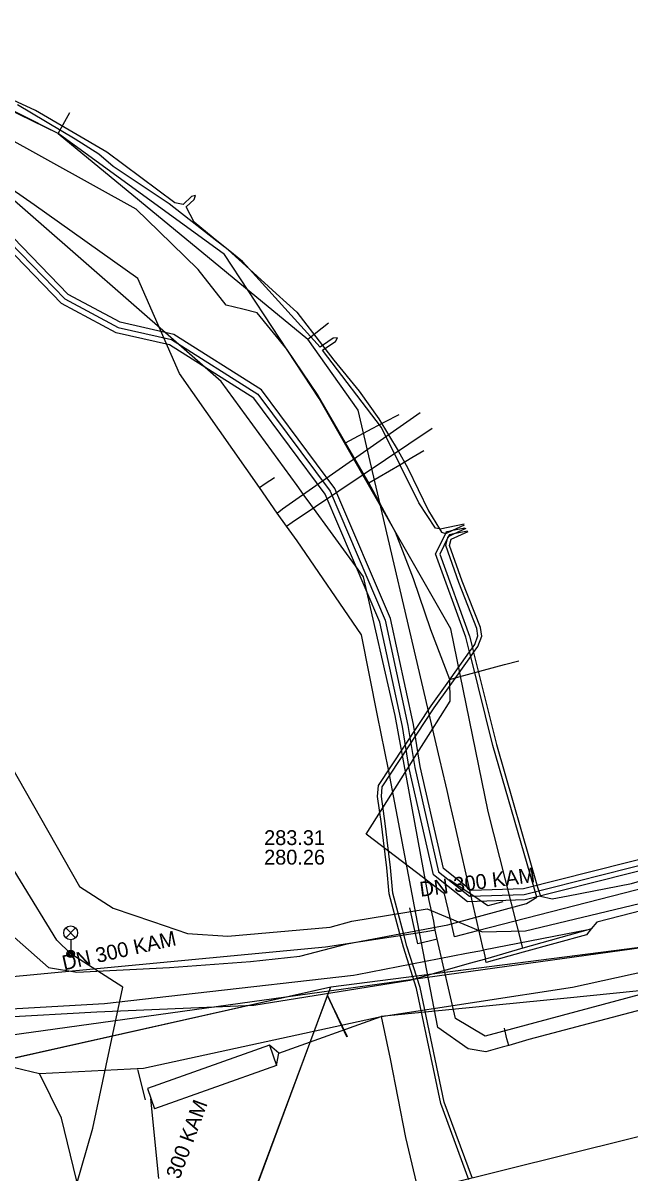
# Model space of a CAD drawing. Extents: x -599854 to -599675, y -1160809 to -1160543.
# Drawn here: x -599745.4 to -599712.8, y -1160609.7 to -1160547.9 of the extents above; entities that cross this region are included whole.
import ezdxf

# ---------------------------------------------------------------- set-up
doc = ezdxf.new("R2010")
doc.units = 0
for name, color, linetype in [('BKOM-ODVODNENI_trasa sítě', 7, 'Continuous'), ('BVK-KANALIZACE_ vyřazená trasa sítě', 7, 'Continuous'), ('BVK-VODOVOD_trasa sítě', 7, 'Continuous'), ('BVK-VODOVOD_trasa zrušené sítě', 7, 'Continuous'), ('CETIN_kabel podzemní', 7, 'Continuous'), ('CETIN_kabel podzemní neprovozovaný', 7, 'Continuous'), ('DESTOVA-NEPROVOZOVANA_popisy', 7, 'Continuous'), ('DESTOVA_trasa neprovozované sítě', 7, 'Continuous'), ('DPMB_kabel', 7, 'Continuous'), ('DPMB_kyneta', 7, 'Continuous'), ('DPMB_trolejové vedení-nosné lano', 7, 'Continuous'), ('DSP-JEDNOTNA-BVK_trasa sítě', 7, 'Continuous'), ('DSP-SDEL-MU_kabel', 7, 'Continuous'), ('EON-NN_kabel', 7, 'Continuous'), ('EON-NN_kabel zrušené sítě', 7, 'Continuous'), ('INNOGY-STL_trasa sítě', 7, 'Continuous'), ('TSB_kabel VO', 7, 'Continuous'), ('TSB_lampy VO', 7, 'Continuous')]:
    doc.layers.add(name, color=color, linetype=linetype)

msp = doc.modelspace()

# ---------------------------------------------------------------- linework, layer by layer
at = {"layer": 'BKOM-ODVODNENI_trasa sítě'}
for points in [[(-599728.85, -1160599.72), (-599710.68, -1160597.38)], [(-599747.14, -1160603.82), (-599728.85, -1160599.72)], [(-599734.15, -1160614), (-599732.8, -1160610.35), (-599728.85, -1160599.72)], [(-599727.954, -1160602.402), (-599729.02, -1160600.18)]]:
    msp.add_lwpolyline(points, dxfattribs=at)
at = {"layer": 'BVK-KANALIZACE_ vyřazená trasa sítě'}
msp.add_line((-599747.65, -1160602.53), (-599706.89, -1160596.87), dxfattribs=at)
at = {"layer": 'BVK-VODOVOD_trasa sítě'}
for points in [[(-599719.633, -1160602.967), (-599720.5, -1160603.21), (-599721.46, -1160603.05), (-599723.09, -1160601.91), (-599724.27, -1160595.77), (-599725.34, -1160590.19), (-599725.75, -1160588.02), (-599726.33, -1160585.11), (-599727.19, -1160580.77), (-599730.66, -1160575.71), (-599731.23, -1160574.92), (-599731.73, -1160574.22), (-599732.69, -1160572.85), (-599736.99, -1160566.71), (-599739.23, -1160561.6), (-599744.81, -1160557.63), (-599749.37, -1160554.46), (-599750.43, -1160553.69), (-599750.93, -1160553.31), (-599752.19, -1160552.51), (-599757.77, -1160552.65), (-599772.65, -1160553.34)], [(-599731.73, -1160574.22), (-599731.44, -1160574), (-599724.05, -1160568.815)], [(-599731.23, -1160574.92), (-599730.92, -1160574.72), (-599723.391, -1160569.647)], [(-599732.69, -1160572.85), (-599732.37, -1160572.63), (-599731.874, -1160572.301)], [(-599684.94, -1160592.81), (-599686.46, -1160593.25), (-599687.27, -1160594.52), (-599690.45, -1160595.29), (-599704.19, -1160598.9), (-599709.92, -1160600.36), (-599718.2, -1160602.56), (-599719.28, -1160602.87), (-599719.633, -1160602.967)], [(-599719.28, -1160602.87), (-599719.373, -1160602.508), (-599719.5, -1160601.95)]]:
    msp.add_lwpolyline(points, dxfattribs=at)
at = {"layer": 'BVK-VODOVOD_trasa zrušené sítě'}
for q in [(-599723.312, -1160596.189), (-599723.722, -1160596.755)]:
    msp.add_line((-599723.241, -1160596.669), q, dxfattribs=at)
for points in [[(-599723.312, -1160596.189), (-599723.552, -1160595.075), (-599725.385, -1160585.124), (-599727.088, -1160577.648), (-599730.061, -1160573.561), (-599730.185, -1160573.396), (-599730.663, -1160572.731), (-599734.747, -1160567.144), (-599747.147, -1160556.314), (-599750.794, -1160554.698), (-599754.863, -1160552.892), (-599773.118, -1160554.584), (-599787.156, -1160555.886), (-599789.075, -1160557.142), (-599798.149, -1160563.04), (-599806.144, -1160568.237), (-599808.168, -1160571.846), (-599815.66, -1160586.425), (-599816.228, -1160587.481)], [(-599684.94, -1160592.81), (-599720.55, -1160602.37), (-599722.14, -1160601.43), (-599723.128, -1160597.158), (-599723.241, -1160596.669)], [(-599723.128, -1160597.158), (-599723.488, -1160597.241), (-599724.166, -1160597.396), (-599724.288, -1160596.841), (-599724.591, -1160595.462)], [(-599723.722, -1160596.755), (-599729.139, -1160597.579), (-599769.626, -1160601.428)], [(-599679.2237, -1160599.5579), (-599732.933, -1160612.912), (-599785.657, -1160621.012)]]:
    msp.add_lwpolyline(points, dxfattribs=at)
at = {"layer": 'CETIN_kabel podzemní'}
for points in [[(-599743.51, -1160553.8), (-599747.69, -1160551.77), (-599759.07, -1160547.85)], [(-599743.51, -1160553.8), (-599742.89, -1160552.67)], [(-599743.51, -1160553.8), (-599730.08, -1160564.86)], [(-599730.08, -1160564.86), (-599728.98, -1160563.98)], [(-599722.66, -1160588.85), (-599722.98, -1160587.49), (-599727.38, -1160568.68), (-599730.08, -1160564.86)], [(-599747.4, -1160585.47), (-599742.37, -1160594.32), (-599740.56, -1160595.49), (-599738.44, -1160596.21), (-599736.55, -1160596.84), (-599734.39, -1160596.99), (-599728.89, -1160596.5), (-599727.72, -1160596.19), (-599723.67, -1160595.52), (-599720.71, -1160596.76), (-599718.38, -1160596.71), (-599712.25, -1160595.23), (-599710.48, -1160595.36)], [(-599722.18, -1160590.96), (-599722.42, -1160589.89), (-599722.59, -1160589.16), (-599722.66, -1160588.85)], [(-599720.64, -1160597.74), (-599721.23, -1160595.16), (-599722.18, -1160590.96)], [(-599710.85, -1160595.28), (-599714.54, -1160596.23), (-599714.84, -1160596.6)], [(-599714.84, -1160596.6), (-599715.1, -1160596.91), (-599718.5, -1160597.86), (-599720.49, -1160598.41), (-599720.53, -1160598.22)], [(-599720.64, -1160597.74), (-599720.53, -1160598.22)]]:
    msp.add_lwpolyline(points, dxfattribs=at)
at = {"layer": 'CETIN_kabel podzemní neprovozovaný'}
for points in [[(-599720.38, -1160590.29), (-599722.4, -1160580.45), (-599729.47, -1160568.06), (-599734.57, -1160560.31), (-599743.51, -1160553.8), (-599747.69, -1160551.7), (-599754.14, -1160548.99)], [(-599718.51, -1160597.64), (-599720.38, -1160590.29)], [(-599715.01, -1160596.65), (-599720.64, -1160597.74)], [(-599715.01, -1160596.65), (-599718.51, -1160597.64)], [(-599714.84, -1160596.6), (-599715.01, -1160596.65)], [(-599736.15, -1160600.06), (-599727.62, -1160599.09), (-599727.43, -1160599.05), (-599721.54, -1160597.91), (-599720.64, -1160597.74)], [(-599718.51, -1160597.64), (-599720.53, -1160598.22)], [(-599720.53, -1160598.22), (-599721.4, -1160598.46), (-599724.59, -1160599.37), (-599732.98, -1160600.73), (-599735.95, -1160600.85), (-599741.43, -1160601.08), (-599746.54, -1160601.36), (-599746.99, -1160601.21), (-599747.63, -1160600.99)], [(-599747.63, -1160600.99), (-599741.02, -1160600.62), (-599736.15, -1160600.06)]]:
    msp.add_lwpolyline(points, dxfattribs=at)
at = {"layer": 'DESTOVA-NEPROVOZOVANA_popisy'}
msp.add_line((-599732.433, -1160593.139), (-599732.433, -1160593.139), dxfattribs=at)
at = {"layer": 'DESTOVA_trasa neprovozované sítě'}
for p, q in [((-599747.14, -1160603.82), (-599728.85, -1160599.72)), ((-599727.98, -1160602.4), (-599729.021, -1160600.181))]:
    msp.add_line(p, q, dxfattribs=at)
for points in [[(-599728.85, -1160599.72), (-599711.672, -1160597.508), (-599710.68, -1160597.38)], [(-599734.15, -1160614), (-599732.963, -1160610.803), (-599732.796, -1160610.353), (-599729.021, -1160600.181), (-599728.85, -1160599.72)]]:
    msp.add_lwpolyline(points, dxfattribs=at)
at = {"layer": 'DPMB_kabel'}
for points in [[(-599746.11, -1160559.64), (-599743.15, -1160562.7), (-599740.29, -1160564.24), (-599737.41, -1160564.89), (-599732.78, -1160567.82), (-599728.89, -1160573.05), (-599725.931, -1160579.993), (-599724.7, -1160585.65), (-599724.33, -1160587.91), (-599723.05, -1160593.52), (-599721.395, -1160594.843), (-599718.44, -1160594.74), (-599712.79, -1160593.31), (-599697.24, -1160589.45), (-599689.48, -1160587.43), (-599686.51, -1160586.61), (-599685.46, -1160586.78), (-599682.03, -1160589.19), (-599679.2237, -1160588.477)], [(-599746.11, -1160559.64), (-599743.15, -1160562.7), (-599740.29, -1160564.24), (-599737.41, -1160564.89), (-599732.78, -1160567.82), (-599728.89, -1160573.05), (-599725.931, -1160579.993), (-599724.7, -1160585.65), (-599724.33, -1160587.91), (-599723.05, -1160593.52), (-599721.395, -1160594.843), (-599718.44, -1160594.74), (-599712.79, -1160593.31), (-599697.24, -1160589.45), (-599689.48, -1160587.43), (-599686.51, -1160586.61), (-599685.46, -1160586.78), (-599682.03, -1160589.19), (-599679.2237, -1160588.477)], [(-599679.2237, -1160588.1676), (-599681.97, -1160588.865), (-599685.344, -1160586.495), (-599686.527, -1160586.303), (-599689.558, -1160587.14), (-599697.314, -1160589.159), (-599712.863, -1160593.019), (-599718.483, -1160594.441), (-599721.294, -1160594.539), (-599722.781, -1160593.351), (-599724.035, -1160587.852), (-599724.405, -1160585.594), (-599725.644, -1160579.901), (-599728.628, -1160572.9), (-599732.573, -1160567.596), (-599737.293, -1160564.609), (-599740.184, -1160563.956), (-599742.967, -1160562.458), (-599745.93, -1160559.394)], [(-599679.2237, -1160588.1676), (-599681.97, -1160588.865), (-599685.344, -1160586.495), (-599686.527, -1160586.303), (-599689.558, -1160587.14), (-599697.314, -1160589.159), (-599712.863, -1160593.019), (-599718.483, -1160594.441), (-599721.294, -1160594.539), (-599722.781, -1160593.351), (-599724.035, -1160587.852), (-599724.405, -1160585.594), (-599725.644, -1160579.901), (-599728.628, -1160572.9), (-599732.573, -1160567.596), (-599737.293, -1160564.609), (-599740.184, -1160563.956), (-599742.967, -1160562.458), (-599745.93, -1160559.394)]]:
    msp.add_lwpolyline(points, dxfattribs=at)
at = {"layer": 'DPMB_kyneta'}
msp.add_lwpolyline([(-599679.2237, -1160588.7865), (-599682.09, -1160589.515), (-599685.576, -1160587.065), (-599686.493, -1160586.917), (-599689.402, -1160587.72), (-599697.166, -1160589.741), (-599712.717, -1160593.601), (-599718.397, -1160595.039), (-599721.496, -1160595.147), (-599723.319, -1160593.689), (-599724.625, -1160587.968), (-599724.995, -1160585.706), (-599726.218, -1160580.085), (-599729.152, -1160573.2), (-599732.987, -1160568.044), (-599737.527, -1160565.171), (-599740.396, -1160564.524), (-599743.333, -1160562.942), (-599746.29, -1160559.886), (-599753.886, -1160556.123), (-599765.587, -1160554.421), (-599775.611, -1160554.72)], dxfattribs=at)
at = {"layer": 'DPMB_trolejové vedení-nosné lano'}
for points in [[(-599715.84, -1160599.73), (-599702.95, -1160596.9)], [(-599702.52, -1160598.95), (-599716.14, -1160600.32)], [(-599726.14, -1160601.32), (-599715.84, -1160599.73)], [(-599716.14, -1160600.32), (-599726.14, -1160601.32)], [(-599738.93, -1160604.09), (-599726.14, -1160601.32)], [(-599731.645, -1160603.286), (-599726.14, -1160601.32)], [(-599726.14, -1160601.32), (-599725.66, -1160603.6)], [(-599751.26, -1160602.76), (-599744.51, -1160604.39)], [(-599732.152, -1160602.853), (-599738.714, -1160605.195)], [(-599732.152, -1160602.853), (-599731.763, -1160603.942), (-599731.645, -1160603.286), (-599732.152, -1160602.853)], [(-599725.66, -1160603.6), (-599724.83, -1160607.82)], [(-599744.51, -1160604.39), (-599738.93, -1160604.09)], [(-599738.81, -1160605.8), (-599739.221, -1160604.162)], [(-599731.763, -1160603.942), (-599735.3, -1160605.2)], [(-599743.34, -1160606.79), (-599744.51, -1160604.39)], [(-599738.714, -1160605.195), (-599738.325, -1160606.284)], [(-599735.3, -1160605.2), (-599738.325, -1160606.284)], [(-599738.1, -1160610.04), (-599738.52, -1160605.74)], [(-599743.34, -1160606.79), (-599743.342, -1160606.788)], [(-599742.37, -1160610.76), (-599743.34, -1160606.79)], [(-599724.83, -1160607.82), (-599723.33, -1160614.17)]]:
    msp.add_lwpolyline(points, dxfattribs=at)
at = {"layer": 'DSP-JEDNOTNA-BVK_trasa sítě'}
for p, q in [((-599728.85, -1160599.72), (-599711.672, -1160597.508)), ((-599747.14, -1160603.82), (-599728.85, -1160599.72)), ((-599729.021, -1160600.181), (-599728.85, -1160599.72)), ((-599732.796, -1160610.353), (-599729.021, -1160600.181)), ((-599729.021, -1160600.181), (-599727.98, -1160602.4))]:
    msp.add_line(p, q, dxfattribs=at)
at = {"layer": 'DSP-SDEL-MU_kabel'}
msp.add_lwpolyline([(-599719.6, -1160595.15), (-599720.4, -1160595.36), (-599721.1, -1160594.87), (-599722.49, -1160593.96)], dxfattribs=at)
at = {"layer": 'EON-NN_kabel'}
for points in [[(-599721.679, -1160574.824), (-599722.965, -1160575.086), (-599722.995, -1160575.079), (-599723.22, -1160575.03), (-599724.11, -1160573.67), (-599726.12, -1160569.61), (-599729.289, -1160565.45), (-599729.166, -1160565.367), (-599728.6, -1160564.985), (-599728.49, -1160564.79), (-599728.712, -1160564.819), (-599729.289, -1160565.208), (-599729.418, -1160565.295), (-599733.214, -1160561.106), (-599733.6, -1160560.68), (-599734.374, -1160560.052), (-599734.975, -1160559.564), (-599736.2, -1160558.57), (-599736.623, -1160557.743), (-599736.197, -1160557.34), (-599736.12, -1160557.13), (-599736.334, -1160557.195), (-599736.787, -1160557.623), (-599737.24, -1160557.52), (-599740.89, -1160554.8), (-599744.73, -1160552.56), (-599749.09, -1160550.55)], [(-599745.7, -1160552.24), (-599742.59, -1160554.08), (-599741.32, -1160554.89), (-599740.56, -1160555.55), (-599737.54, -1160557.57), (-599734.975, -1160559.564), (-599734.53, -1160559.91), (-599734.374, -1160560.052), (-599733.214, -1160561.106), (-599731.79, -1160562.4), (-599730.67, -1160563.41), (-599729.289, -1160565.208), (-599729.166, -1160565.367), (-599728.68, -1160566), (-599727.33, -1160567.67), (-599726.27, -1160569.16), (-599725.23, -1160570.88), (-599724.7, -1160571.81), (-599723.6, -1160574.1), (-599722.995, -1160575.079), (-599722.89, -1160575.25), (-599722.683, -1160575.329), (-599722.666, -1160575.321), (-599722.285, -1160575.149), (-599721.656, -1160574.864)], [(-599721.425, -1160610.103), (-599722.936, -1160605.988), (-599724.237, -1160599.806), (-599724.946, -1160597.578), (-599725.135, -1160596.87), (-599725.709, -1160594.718), (-599725.839, -1160593.32), (-599726.009, -1160591.842), (-599726.119, -1160590.953), (-599726.331, -1160589.473), (-599726.288, -1160588.887), (-599723.452, -1160584.593), (-599722.581, -1160583.392), (-599721.381, -1160581.69), (-599721.229, -1160581.473), (-599721.109, -1160581.303), (-599720.933, -1160580.829), (-599720.987, -1160580.436), (-599721.964, -1160577.965), (-599722.664, -1160575.974), (-599722.553, -1160575.544), (-599722.537, -1160575.483), (-599722.519, -1160575.475), (-599722.223, -1160575.341), (-599721.56, -1160575.04)], [(-599721.235, -1160610.037), (-599722.744, -1160605.932), (-599724.043, -1160599.754), (-599724.754, -1160597.522), (-599724.938, -1160596.833), (-599725.511, -1160594.682), (-599725.641, -1160593.3), (-599725.811, -1160591.818), (-599725.921, -1160590.927), (-599726.129, -1160589.467), (-599726.092, -1160588.953), (-599723.288, -1160584.707), (-599722.419, -1160583.508), (-599721.318, -1160581.945), (-599721.165, -1160581.729), (-599720.931, -1160581.397), (-599720.727, -1160580.851), (-599720.793, -1160580.384), (-599721.776, -1160577.895), (-599722.456, -1160575.966), (-599722.367, -1160575.626), (-599721.464, -1160575.216)], [(-599721.503, -1160575.197), (-599722.223, -1160575.341), (-599722.478, -1160575.392), (-599722.519, -1160575.475), (-599722.553, -1160575.544), (-599722.991, -1160576.436), (-599721.384, -1160580.851), (-599721.229, -1160581.473), (-599721.165, -1160581.729), (-599719.933, -1160586.674), (-599717.724, -1160594.352), (-599717.574, -1160594.841), (-599716.94, -1160594.98), (-599716.085, -1160594.816), (-599712.67, -1160594.16), (-599704.71, -1160591.83), (-599697.42, -1160590.02), (-599692.077, -1160588.556), (-599692.166, -1160588.271), (-599692.13, -1160588.05), (-599691.975, -1160588.211), (-599691.882, -1160588.508), (-599685.56, -1160587.08), (-599679.2237, -1160585.3638)]]:
    msp.add_lwpolyline(points, dxfattribs=at)
at = {"layer": 'EON-NN_kabel zrušené sítě'}
msp.add_lwpolyline([(-599747.43, -1160595.7), (-599744.03, -1160598.67), (-599742.51, -1160598.92), (-599737.52, -1160598.67), (-599733.17, -1160598.36), (-599730.51, -1160598.06), (-599727.97, -1160597.41), (-599725.135, -1160596.87), (-599724.938, -1160596.833), (-599722.56, -1160596.38), (-599719.447, -1160595.536), (-599718.32, -1160595.23), (-599717.766, -1160594.899), (-599720.127, -1160586.726), (-599721.318, -1160581.945), (-599721.381, -1160581.69), (-599721.576, -1160580.909), (-599723.209, -1160576.424), (-599722.666, -1160575.321), (-599722.618, -1160575.223), (-599722.49, -1160575.19), (-599722.285, -1160575.149), (-599721.64, -1160575.02)], dxfattribs=at)
at = {"layer": 'INNOGY-STL_trasa sítě'}
for points in [[(-599722.2, -1160597.03), (-599722.45, -1160595.92), (-599722.73, -1160594.71), (-599726.95, -1160591.5), (-599724.51, -1160587.65), (-599724.34, -1160587.38), (-599723.46, -1160585.99), (-599722.42, -1160584.35), (-599722.45, -1160583.17), (-599723.47, -1160580.5), (-599724.4, -1160577.77), (-599725.36, -1160575.25), (-599726.81, -1160572.6), (-599728.05, -1160570.44), (-599729.56, -1160567.85), (-599731.21, -1160565.4), (-599732.81, -1160563.44), (-599733.58, -1160563.25), (-599734.47, -1160563.03), (-599735.98, -1160561.12), (-599738.1, -1160559.05), (-599739.31, -1160557.87), (-599749, -1160552.5)], [(-599728.05, -1160570.44), (-599726.62, -1160569.68), (-599725.94, -1160569.32), (-599725.17, -1160568.91)], [(-599726.81, -1160572.6), (-599725.14, -1160571.62), (-599724.49, -1160571.24), (-599723.84, -1160570.86)], [(-599722.45, -1160583.17), (-599721.97, -1160583.04), (-599719.5, -1160582.38), (-599718.74, -1160582.18)], [(-599679.2237, -1160585.8252), (-599684.66, -1160587.24), (-599689.7, -1160588.59), (-599691.13, -1160588.96), (-599698.11, -1160590.8), (-599700.46, -1160591.4), (-599704.95, -1160592.57), (-599711.11, -1160594.18), (-599720.96, -1160596.71), (-599722.2, -1160597.03)]]:
    msp.add_lwpolyline(points, dxfattribs=at)
at = {"layer": 'TSB_kabel VO'}
msp.add_lwpolyline([(-599712.85, -1160612.2), (-599713.231, -1160610.818), (-599715.05, -1160611.32), (-599720.13, -1160612.91), (-599729.8, -1160616.03), (-599730.26, -1160617.21), (-599734.33, -1160617.68), (-599739.29, -1160617.63), (-599739.48, -1160618.61), (-599740.14, -1160618.47), (-599744.95, -1160617.17), (-599744.01, -1160615.53), (-599741.64, -1160607.33), (-599740.03, -1160599.74), (-599742.84, -1160597.94), (-599743.59, -1160597.21), (-599749.46, -1160587.62), (-599756.62, -1160578.69), (-599758.16, -1160577.35), (-599762.32, -1160572.73), (-599766.71, -1160568.47)], dxfattribs=at)
at = {"layer": 'TSB_lampy VO'}
for p, q in [((-599743.105, -1160597.08), (-599742.575, -1160596.55)), ((-599743.105, -1160596.55), (-599742.575, -1160597.08)), ((-599743.105, -1160597.08), (-599742.575, -1160596.55)), ((-599743.105, -1160596.55), (-599742.575, -1160597.08)), ((-599742.84, -1160597.19), (-599742.84, -1160597.94)), ((-599742.84, -1160597.19), (-599742.84, -1160597.94))]:
    msp.add_line(p, q, dxfattribs=at)
for centre, radius in [((-599742.84, -1160596.815), 0.375), ((-599742.84, -1160596.815), 0.375), ((-599742.84, -1160597.94), 0.2), ((-599742.84, -1160597.94), 0.2), ((-599742.84, -1160597.94), 0.1445), ((-599742.84, -1160597.94), 0.1445), ((-599742.84, -1160597.94), 0.0876), ((-599742.84, -1160597.94), 0.0876)]:
    msp.add_circle(centre, radius, dxfattribs=at)

# ---------------------------------------------------------------- texts
at = {"layer": 'DESTOVA-NEPROVOZOVANA_popisy'}
for s, p in [('283.31', (-599732.433, -1160592.089)), ('280.26', (-599732.433, -1160593.139))]:
    msp.add_text(s, height=0.8, dxfattribs=at).set_placement(p)
for rotation, p in [(7.338369, (-599724.018, -1160594.873)), (12.6349, (-599743.198, -1160598.837)), (69.637669, (-599737.63, -1160611.842))]:
    msp.add_text('DN 300 KAM', height=0.8, rotation=rotation, dxfattribs=at).set_placement(p)

doc.saveas('drawing.dxf')
